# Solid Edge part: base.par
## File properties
Title: Base
Author: Abhinav Rai
Template: Normal.par
Last saved by: CADCIM
Revision: 24
Application: Solid Edge
Material: aluminum
Accuracy: 0.99
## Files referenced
..\Asm2.asm
/D:\solid_edge_18\c09_sld_edg_18_030606\Asm2.asm
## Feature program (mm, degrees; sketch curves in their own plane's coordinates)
sketch for "unnamed Protrusion 1" plane through (0, 0, 0) normal (1, 0, 0) x-axis (0, 1, 0)
  line (-34.925, 42.0624) -> (-34.925, -42.0624)
  line (-15.875, -42.0624) -> (-34.925, -42.0624)
  line (-15.875, -42.0624) -> (-15.875, -15.0876)
  line (-15.875, -15.0876) -> (-12.7, -15.0876)
  line (-12.7, -15.0876) -> (-12.7, 0.8001)
  line (-12.7, 0.8001) -> (12.7, 0.8001)
  line (12.7, 0.8001) -> (12.7, -15.0876)
  line (12.7, -15.0876) -> (15.875, -15.0876)
  line (15.875, -15.0876) -> (15.875, -42.0624)
  line (15.875, -42.0624) -> (34.925, -42.0624)
  line (34.925, -42.0624) -> (34.925, 42.0624)
  line (34.925, 42.0624) -> (-34.925, 42.0624)
  dimension (linear) = 15.875
extrude "unnamed Protrusion 1" add finite 184.15 along -normal
sketch for "unnamed Cutout 1" plane through (-92.075, -34.925, 0) normal (0, -1, 0) x-axis (1, 0, 0)
  line (-60.325, 58.9033) -> (-60.325, -2.3876)
  line (-60.325, -2.3876) -> (66.675, -2.3876)
  line (66.675, -2.3876) -> (66.675, 32.5374)
  line (66.675, 32.5374) -> (138.7184, 32.5374)
  line (138.7184, 32.5374) -> (138.7184, 58.9033)
  line (-60.325, 58.9033) -> (138.7184, 58.9033)
extrude "unnamed Cutout 1" cut through along -normal
sketch for "ExtrudedCutout_2" plane through (0, 0, -4.3434) normal (1, 0, 0) x-axis (0, 1, 0)
  line (18.2179, 17.8308) -> (34.925, 17.8308)
  line (42.2755, 17.8308) -> (34.925, 17.8308)
  line (42.2755, 51.2375) -> (42.2755, 17.8308)
  line (-47.5259, 51.2375) -> (42.2755, 51.2375)
  line (-47.5259, 17.8308) -> (-47.5259, 51.2375)
  line (-34.925, 17.8308) -> (-47.5259, 17.8308)
  line (-34.925, 17.8308) -> (-18.2179, 17.8308)
  arc centre (0, 18.6448) radius 18.236 from (-18.2179, 17.8308) to (18.2179, 17.8308) cw
extrude "ExtrudedCutout_2" cut finite 76.2 along -normal
sketch for "Hole_1" plane through (0, 0, -4.7625) normal (1, 0, 0) x-axis (0, 1, 0)
  hole centre (0, 19.0639) bore radius 7.9375
hole "Hole_1" diameter 15.875 through
fillet "Round_2" radius 34.925
sketch for "ExtrudedProtrusion_2" plane through (-92.075, -25.4, -42.0624) normal (0, 0, -1) x-axis (1, 0, 0)
  arc centre (63.5638, -62.2328) radius 28.575 from (92.075, -60.325) to (35.0525, -60.325) cw
  line (35.4, -60.325) -> (92.075, -60.325)
extrude "ExtrudedProtrusion_2" add finite 7.9248 along -normal
sketch for "Hole_2" plane through (-31.5444, 50.1664, -34.1376) normal (0, 0, 1) x-axis (-1, 0, 0)
hole "Hole_2" diameter 7.9248 through
mirror "unnamed Mirror 1" of "ExtrudedProtrusion_2", "Hole_2" about plane through (-92.075, 0, 0) normal (1, 0, 0)
extrude "unnamed Protrusion 2" add finite 7.9248
hole "unnamed Hole 1" through
mirror "unnamed Mirror 2" of "ExtrudedProtrusion_2", "Hole_2", "unnamed Mirror 1" about plane through (0, 0, 0) normal (0, -1, 0)
extrude "unnamed Protrusion 3" add finite 7.9248
hole "unnamed Hole 2" through
extrude "unnamed Protrusion 4" add finite 7.9248
hole "unnamed Hole 3" through
sketch for "Hole_28" plane through (-152.4, 0, 15.5518) normal (1, 0, 0) x-axis (0, 1, 0)
  hole centre (19.05, 7.4606) bore radius 3.175
hole "Hole_28" diameter 6.35 finite
sketch for "unnamed Hole 4" plane through (-152.4, 0, 15.5518) normal (1, 0, 0) x-axis (0, 1, 0)
  hole centre (-19.05, 7.4606) bore radius 3.175
  dimension (linear) = 19.05
  dimension (linear) = 19.05
hole "unnamed Hole 4" finite
pattern "unnamed Pattern 1" of "Hole_28", "unnamed Hole 4"
fillet "Round_24" radius 3.81
hole "Hole_30" diameter 6.35 through
hole "unnamed Hole 5" through
hole "unnamed Hole 6" through
pattern "unnamed Pattern 2" of "Hole_30", "unnamed Hole 5", "unnamed Hole 6"
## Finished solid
Body 1: solid body, 94 faces, 227 edges, 122 vertices.
  Faces by surface: cylinder 41, plane 26, torus 13, blend 12, sphere 2
  Edges by curve: circle 105, line 96, intersection 26
Bounding box of the edges (mm; curved faces can reach further): 184.280 x 130.816 x 84.125, from (-184.2151, -65.4078, -42.0624) to (0.0651, 65.4078, 42.0624).
Cylindrical faces by radius (mm): R3.175 x8, R3.81 x22, R3.9624 x4, R7.9375 x1, R18.236 x1, R28.575 x4, R34.925 x1
Toroidal faces (ring radius, tube radius in mm): R7.62 r3.81 x6, R14.426 r3.81 x1, R24.765 r3.81 x4, R31.115 r3.81 x2
Spherical faces by radius (mm): R3.81 x2
Planar faces by outward normal: +x 4, +y 3, +z 8, -x 2, -y 3, -z 6
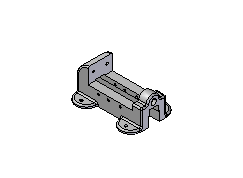
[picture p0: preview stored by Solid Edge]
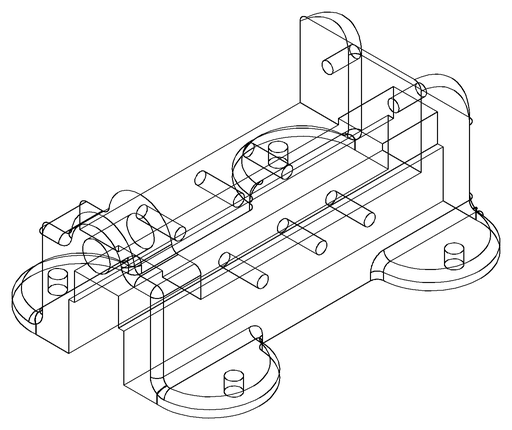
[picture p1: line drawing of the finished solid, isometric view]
